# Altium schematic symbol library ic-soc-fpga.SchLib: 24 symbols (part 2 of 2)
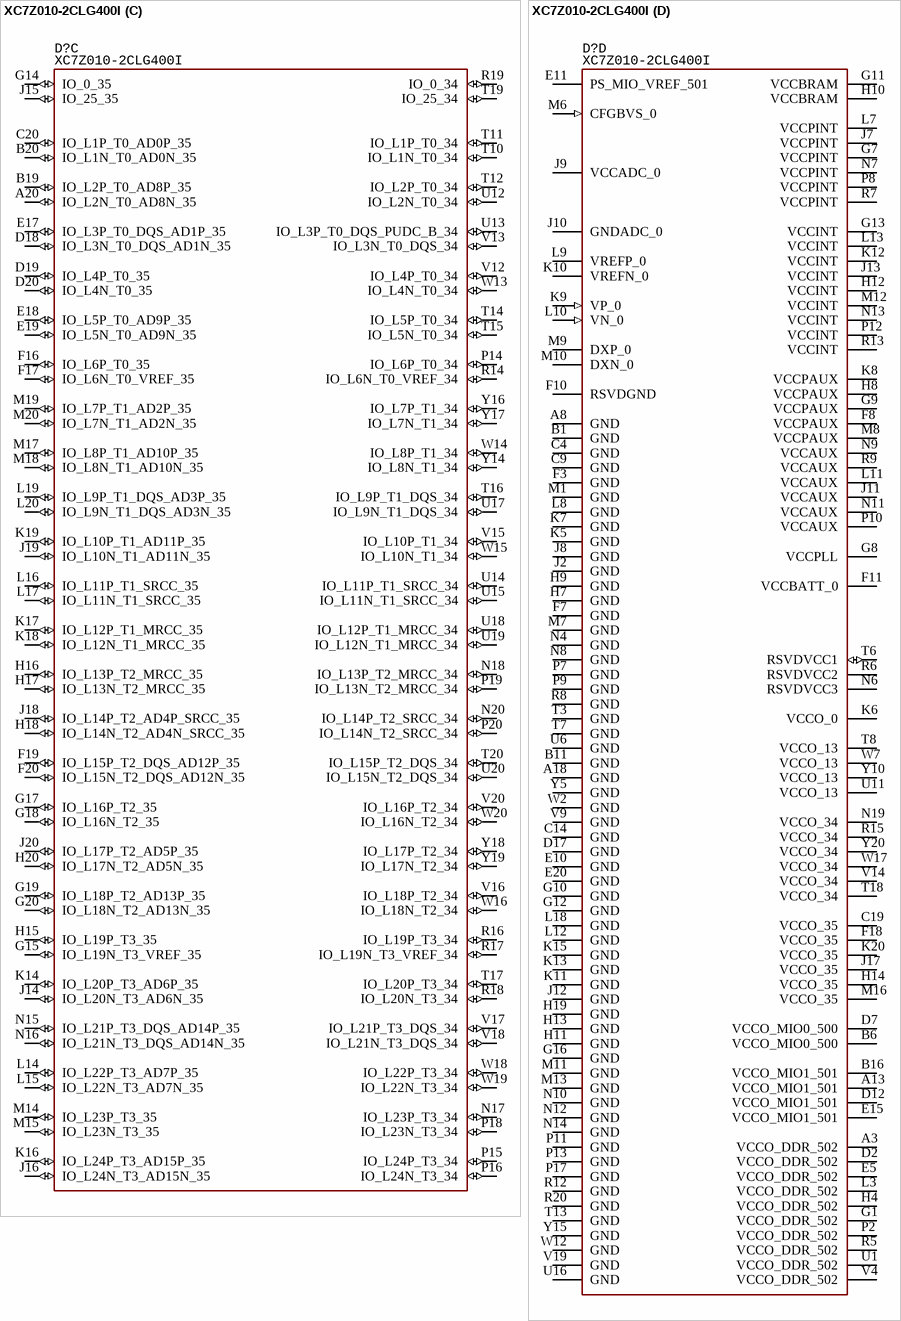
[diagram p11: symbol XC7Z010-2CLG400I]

## XC7Z010-2CLG400I
designator D?
SoC ARM + FPGA, 766MHz, 28k LUT, CSBGA-400, -40...+100°C; Manufacturer: Xilinx
footprint 400-FBGA (pitch 0.8 mm)
part A pins: A5 PS_MIO6_500 (io), A6 PS_MIO5_500 (io), A7 PS_MIO1_500 (io), A9 PS_MIO43_501 (io), A10 PS_MIO37_501 (io), A11 PS_MIO36_501 (io), A12 PS_MIO34_501 (io), A14 PS_MIO32_501 (io), A15 PS_MIO26_501 (io), A16 PS_MIO24_501 (io), A17 PS_MIO20_501 (io), A19 PS_MIO16_501 (io), B5 PS_MIO9_500 (io), B7 PS_MIO4_500 (io), B8 PS_MIO2_500 (io), B9 PS_MIO51_501 (io), B10 PS_SRST_B_501 (in), B12 PS_MIO48_501 (io), B13 PS_MIO50_501 (io), B14 PS_MIO47_501 (io), B15 PS_MIO45_501 (io), B17 PS_MIO22_501 (io), B18 PS_MIO18_501 (io), C5 PS_MIO14_500 (io), C6 PS_MIO11_500 (io), C7 PS_POR_B_500 (in), C8 PS_MIO15_500 (io), C10 PS_MIO52_501 (io), C11 PS_MIO53_501 (io), C12 PS_MIO49_501 (io), C13 PS_MIO29_501 (io), C15 PS_MIO30_501 (io), C16 PS_MIO28_501 (io), C17 PS_MIO41_501 (io), C18 PS_MIO39_501 (io), D5 PS_MIO8_500 (io), D6 PS_MIO3_500 (io), D8 PS_MIO7_500 (io), D9 PS_MIO12_500 (io), D10 PS_MIO19_501 (io), D11 PS_MIO23_501 (io), D13 PS_MIO27_501 (io), D14 PS_MIO40_501 (io), D15 PS_MIO33_501 (io), D16 PS_MIO46_501 (io), E6 PS_MIO0_500 (io), E7 PS_CLK_500 (in), E8 PS_MIO13_500 (io), E9 PS_MIO10_500 (io), E12 PS_MIO42_501 (io), E13 PS_MIO38_501 (io), E14 PS_MIO17_501 (io), E16 PS_MIO31_501 (io), F6 TDO_0 (out), F9 TCK_0 (in), F12 PS_MIO35_501 (io), F13 PS_MIO44_501 (io), F14 PS_MIO21_501 (io), F15 PS_MIO25_501 (io), G6 TDI_0 (in), J6 TMS_0 (in), L6 PROGRAM_B_0 (in), R10 INIT_B_0 (io), R11 DONE_0 (io)
part B pins: A1 PS_DDR_DM0_502 (out), A2 PS_DDR_DQ2_502 (io), A4 PS_DDR_DQ3_502 (io), B2 PS_DDR_DQS_N0_502 (io), B3 PS_DDR_DQ1_502 (io), B4 PS_DDR_DRST_B_502 (out), C1 PS_DDR_DQ6_502 (io), C2 PS_DDR_DQS_P0_502 (io), C3 PS_DDR_DQ0_502 (io), D1 PS_DDR_DQ5_502 (io), D3 PS_DDR_DQ4_502 (io), D4 PS_DDR_A13_502 (out), E1 PS_DDR_DQ7_502 (io), E2 PS_DDR_DQ8_502 (io), E3 PS_DDR_DQ9_502 (io), E4 PS_DDR_A12_502 (out), F1 PS_DDR_DM1_502 (out), F2 PS_DDR_DQS_N1_502 (io), F4 PS_DDR_A14_502 (out), F5 PS_DDR_A10_502 (out), G2 PS_DDR_DQS_P1_502 (io), G3 PS_DDR_DQ10_502 (io), G4 PS_DDR_A11_502 (out), G5 PS_DDR_VRN_502 (out), H1 PS_DDR_DQ14_502 (io), H2 PS_DDR_DQ13_502 (io), H3 PS_DDR_DQ11_502 (io), H5 PS_DDR_VRP_502 (out), H6 PS_DDR_VREF0_502 (power), J1 PS_DDR_DQ15_502 (io), J3 PS_DDR_DQ12_502 (io), J4 PS_DDR_A9_502 (out), J5 PS_DDR_BA2_502 (out), K1 PS_DDR_A8_502 (out), K2 PS_DDR_A1_502 (out), K3 PS_DDR_A3_502 (out), K4 PS_DDR_A7_502 (out), L1 PS_DDR_A5_502 (out), L2 PS_DDR_CKP_502 (out), L4 PS_DDR_A6_502 (out), L5 PS_DDR_BA0_502 (out), M2 PS_DDR_CKN_502 (out), M3 PS_DDR_A2_502 (out), M4 PS_DDR_A4_502 (out), M5 PS_DDR_WE_B_502 (out), N1 PS_DDR_CS_B_502 (out), N2 PS_DDR_A0_502 (out), N3 PS_DDR_CKE_502 (out), N5 PS_DDR_ODT_502 (out), P1 PS_DDR_DQ16_502 (io), P3 PS_DDR_DQ17_502 (io), P4 PS_DDR_RAS_B_502 (out), P5 PS_DDR_CAS_B_502 (out), P6 PS_DDR_VREF1_502 (power), R1 PS_DDR_DQ19_502 (io), R2 PS_DDR_DQS_P2_502 (io), R3 PS_DDR_DQ18_502 (io), R4 PS_DDR_BA1_502 (out), T1 PS_DDR_DM2_502 (out), T2 PS_DDR_DQS_N2_502 (io), T4 PS_DDR_DQ20_502 (io), U2 PS_DDR_DQ22_502 (io), U3 PS_DDR_DQ23_502 (io), U4 PS_DDR_DQ21_502 (io), V1 PS_DDR_DQ24_502 (io), V2 PS_DDR_DQ30_502 (io), V3 PS_DDR_DQ31_502 (io), W1 PS_DDR_DQ26_502 (io), W3 PS_DDR_DQ29_502 (io), W4 PS_DDR_DQS_N3_502 (io), W5 PS_DDR_DQS_P3_502 (io), Y1 PS_DDR_DM3_502 (out), Y2 PS_DDR_DQ28_502 (io), Y3 PS_DDR_DQ25_502 (io), Y4 PS_DDR_DQ27_502 (io)
part C pins: A20 IO_L2N_T0_AD8N_35 (io), B19 IO_L2P_T0_AD8P_35 (io), B20 IO_L1N_T0_AD0N_35 (io), C20 IO_L1P_T0_AD0P_35 (io), D18 IO_L3N_T0_DQS_AD1N_35 (io), D19 IO_L4P_T0_35 (io), D20 IO_L4N_T0_35 (io), E17 IO_L3P_T0_DQS_AD1P_35 (io), E18 IO_L5P_T0_AD9P_35 (io), E19 IO_L5N_T0_AD9N_35 (io), F16 IO_L6P_T0_35 (io), F17 IO_L6N_T0_VREF_35 (io), F19 IO_L15P_T2_DQS_AD12P_35 (io), F20 IO_L15N_T2_DQS_AD12N_35 (io), G14 IO_0_35 (io), G15 IO_L19N_T3_VREF_35 (io), G17 IO_L16P_T2_35 (io), G18 IO_L16N_T2_35 (io), G19 IO_L18P_T2_AD13P_35 (io), G20 IO_L18N_T2_AD13N_35 (io), H15 IO_L19P_T3_35 (io), H16 IO_L13P_T2_MRCC_35 (io), H17 IO_L13N_T2_MRCC_35 (io), H18 IO_L14N_T2_AD4N_SRCC_35 (io), H20 IO_L17N_T2_AD5N_35 (io), J14 IO_L20N_T3_AD6N_35 (io), J15 IO_25_35 (io), J16 IO_L24N_T3_AD15N_35 (io), J18 IO_L14P_T2_AD4P_SRCC_35 (io), J19 IO_L10N_T1_AD11N_35 (io), J20 IO_L17P_T2_AD5P_35 (io), K14 IO_L20P_T3_AD6P_35 (io), K16 IO_L24P_T3_AD15P_35 (io), K17 IO_L12P_T1_MRCC_35 (io), K18 IO_L12N_T1_MRCC_35 (io), K19 IO_L10P_T1_AD11P_35 (io), L14 IO_L22P_T3_AD7P_35 (io), L15 IO_L22N_T3_AD7N_35 (io), L16 IO_L11P_T1_SRCC_35 (io), L17 IO_L11N_T1_SRCC_35 (io), L19 IO_L9P_T1_DQS_AD3P_35 (io), L20 IO_L9N_T1_DQS_AD3N_35 (io), M14 IO_L23P_T3_35 (io), M15 IO_L23N_T3_35 (io), M17 IO_L8P_T1_AD10P_35 (io), M18 IO_L8N_T1_AD10N_35 (io), M19 IO_L7P_T1_AD2P_35 (io), M20 IO_L7N_T1_AD2N_35 (io), N15 IO_L21P_T3_DQS_AD14P_35 (io), N16 IO_L21N_T3_DQS_AD14N_35 (io), N17 IO_L23P_T3_34 (io), N18 IO_L13P_T2_MRCC_34 (io), N20 IO_L14P_T2_SRCC_34 (io), P14 IO_L6P_T0_34 (io), P15 IO_L24P_T3_34 (io), P16 IO_L24N_T3_34 (io), P18 IO_L23N_T3_34 (io), P19 IO_L13N_T2_MRCC_34 (io), P20 IO_L14N_T2_SRCC_34 (io), R14 IO_L6N_T0_VREF_34 (io), R16 IO_L19P_T3_34 (io), R17 IO_L19N_T3_VREF_34 (io), R18 IO_L20N_T3_34 (io), R19 IO_0_34 (io), T10 IO_L1N_T0_34 (io), T11 IO_L1P_T0_34 (io), T12 IO_L2P_T0_34 (io), T14 IO_L5P_T0_34 (io), T15 IO_L5N_T0_34 (io), T16 IO_L9P_T1_DQS_34 (io), T17 IO_L20P_T3_34 (io), T19 IO_25_34 (io), T20 IO_L15P_T2_DQS_34 (io), U12 IO_L2N_T0_34 (io), U13 IO_L3P_T0_DQS_PUDC_B_34 (io), U14 IO_L11P_T1_SRCC_34 (io), U15 IO_L11N_T1_SRCC_34 (io), U17 IO_L9N_T1_DQS_34 (io), U18 IO_L12P_T1_MRCC_34 (io), U19 IO_L12N_T1_MRCC_34 (io), U20 IO_L15N_T2_DQS_34 (io), V12 IO_L4P_T0_34 (io), V13 IO_L3N_T0_DQS_34 (io), V15 IO_L10P_T1_34 (io), V16 IO_L18P_T2_34 (io), V17 IO_L21P_T3_DQS_34 (io), V18 IO_L21N_T3_DQS_34 (io), V20 IO_L16P_T2_34 (io), W13 IO_L4N_T0_34 (io), W14 IO_L8P_T1_34 (io), W15 IO_L10N_T1_34 (io), W16 IO_L18N_T2_34 (io), W18 IO_L22P_T3_34 (io), W19 IO_L22N_T3_34 (io), W20 IO_L16N_T2_34 (io), Y14 IO_L8N_T1_34 (io), Y16 IO_L7P_T1_34 (io), Y17 IO_L7N_T1_34 (io), Y18 IO_L17P_T2_34 (io), Y19 IO_L17N_T2_34 (io)
part D pins: A3 VCCO_DDR_502 (power), A8 GND, A13 VCCO_MIO1_501 (power), A18 GND, B1 GND, B6 VCCO_MIO0_500 (power), B11 GND, B16 VCCO_MIO1_501 (power), C4 GND, C9 GND, C14 GND, C19 VCCO_35 (power), D2 VCCO_DDR_502 (power), D7 VCCO_MIO0_500 (power), D12 VCCO_MIO1_501 (power), D17 GND, E5 VCCO_DDR_502 (power), E10 GND, E11 PS_MIO_VREF_501 (power), E15 VCCO_MIO1_501 (power), E20 GND, F3 GND, F7 GND, F8 VCCPAUX (power), F10 RSVDGND, F11 VCCBATT_0 (power), F18 VCCO_35 (power), G1 VCCO_DDR_502 (power), G7 VCCPINT (power), G8 VCCPLL (power), G9 VCCPAUX (power), G10 GND, G11 VCCBRAM (power), G12 GND, G13 VCCINT (power), G16 GND, H4 VCCO_DDR_502 (power), H7 GND, H8 VCCPAUX (power), H9 GND, H10 VCCBRAM (power), H11 GND, H12 VCCINT (power), H13 GND, H14 VCCO_35 (power), H19 GND, J2 GND, J7 VCCPINT (power), J8 GND, J9 VCCADC_0 (power), J10 GNDADC_0, J11 VCCAUX (power), J12 GND, J13 VCCINT (power), J17 VCCO_35 (power), K5 GND, K6 VCCO_0 (power), K7 GND, K8 VCCPAUX (power), K9 VP_0 (in), K10 VREFN_0 (power), K11 GND, K12 VCCINT (power), K13 GND, K15 GND, K20 VCCO_35 (power), L3 VCCO_DDR_502 (power), L7 VCCPINT (power), L8 GND, L9 VREFP_0 (power), L10 VN_0 (in), L11 VCCAUX (power), L12 GND, L13 VCCINT (power), L18 GND, M1 GND, M6 CFGBVS_0 (in), M7 GND, M8 VCCPAUX (power), M9 DXP_0, M10 DXN_0, M11 GND, M12 VCCINT (power), M13 GND, M16 VCCO_35 (power), N4 GND, N6 RSVDVCC3 (power), N7 VCCPINT (power), N8 GND, N9 VCCAUX (power), N10 GND, N11 VCCAUX (power), N12 GND, N13 VCCINT (power), N14 GND, N19 VCCO_34 (power), P2 VCCO_DDR_502 (power), P7 GND, P8 VCCPINT (power), P9 GND, P10 VCCAUX (power), P11 GND, P12 VCCINT (power), P13 GND, P17 GND, R5 VCCO_DDR_502 (power), R6 RSVDVCC2 (power), R7 VCCPINT (power), R8 GND, R9 VCCAUX (power), R12 GND, R13 VCCINT (power), R15 VCCO_34 (power), R20 GND, T3 GND, T6 RSVDVCC1 (io), T7 GND, T8 VCCO_13 (power), T13 GND, T18 VCCO_34 (power), U1 VCCO_DDR_502 (power), U6 GND, U11 VCCO_13 (power), U16 GND, V4 VCCO_DDR_502 (power), V9 GND, V14 VCCO_34 (power), V19 GND, W2 GND, W7 VCCO_13 (power), W12 GND, W17 VCCO_34 (power), Y5 GND, Y10 VCCO_13 (power), Y15 GND, Y20 VCCO_34 (power)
